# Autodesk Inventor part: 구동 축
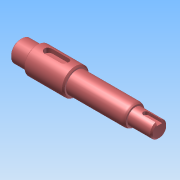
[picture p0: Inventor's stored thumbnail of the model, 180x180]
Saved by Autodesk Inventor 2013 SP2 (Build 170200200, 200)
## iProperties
Created: 2026-10
Part Number: 구동 축
Material: Generic
Document SubType Name: Modeling
Designer: a
Density: 1 g/cm^3
Author: a
변환 표준: STEP AP214IS
전처리기: Build: 200, Release: 2013 SP2 Update 6 - Date: Thu 07/17/2014
전송 단위: 밀리미터
불확실성: 0.01
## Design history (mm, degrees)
node "구동 축1"
node "솔리드1"
node "기준1"
